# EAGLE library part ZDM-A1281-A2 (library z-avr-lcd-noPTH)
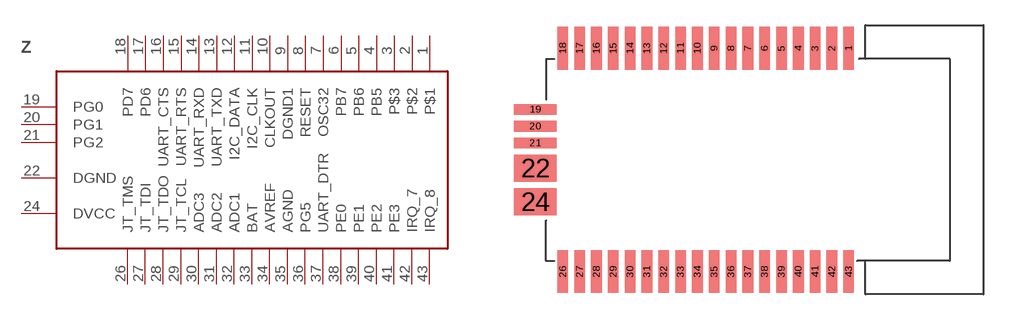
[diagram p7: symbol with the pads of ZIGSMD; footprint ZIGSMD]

Designator prefix Z

## ZDM-A1281-A2N  [ZIGSMD]
1  P$1  nc
2  P$2  nc
3  P$3  nc
4  PB5
5  PB6
6  PB7
7  OSC32  out
8  RESET  in
9  DGND1
10  CLKOUT  out
11  I2C_CLK  out
12  I2C_DATA
13  UART_TXD  in
14  UART_RXD  out
15  UART_RTS  in
16  UART_CTS  out
17  PD6
18  PD7
19  PG0
20  PG1
21  PG2
22  DGND
24  DVCC
26  JT_TMS
27  JT_TDI
28  JT_TDO
29  JT_TCL
30  ADC3  in
31  ADC2  in
32  ADC1  in
33  BAT  in
34  AVREF
35  AGND
36  PG5
37  UART_DTR  in
38  PE0
39  PE1
40  PE2
41  PE3
42  IRQ_7  in
43  IRQ_8  in

## Footprint ZIGSMD (pad centres in mm)
smd 0.635 x 2.54: 1 7,6.635; 2 6,6.635; 3 5,6.635; 4 4,6.635; 5 3,6.635; 6 2,6.635; 7 1,6.635; 8 0,6.635; 9 -1,6.635; 10 -2,6.635; 11 -3,6.635; 12 -4,6.635; 13 -5,6.635; 14 -6,6.635; 15 -7,6.635; 16 -8,6.635; 17 -9,6.635; 18 -10,6.635; 26 -10,-6.635; 27 -9,-6.635; 28 -8,-6.635; 29 -7,-6.635; 30 -6,-6.635; 31 -5,-6.635; 32 -4,-6.635; 33 -3,-6.635; 34 -2,-6.635; 35 -1,-6.635; 36 0,-6.635; 37 1,-6.635; 38 2,-6.635; 39 3,-6.635; 40 4,-6.635; 41 5,-6.635; 42 6,-6.635; 43 7,-6.635
smd 2.54 x 0.635: 19 -11.635,3; 20 -11.635,2; 21 -11.635,1
smd 2.54 x 1.6: 22 -11.635,-0.5; 24 -11.635,-2.5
